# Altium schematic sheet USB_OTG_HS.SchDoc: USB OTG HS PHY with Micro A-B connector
size A4; Date: 25-FEB-2015; Author: A.B; CompanyName: STMicroelectronics; Address1: 12, Rue Jules HOROWITZ; Address2: 38019 Grenoble; Address3: FRANCE; DocumentNumber: MB1191; Revision: B-02; SheetNumber: 10; SheetTotal: 13; Project: STM32F746G-DISCO
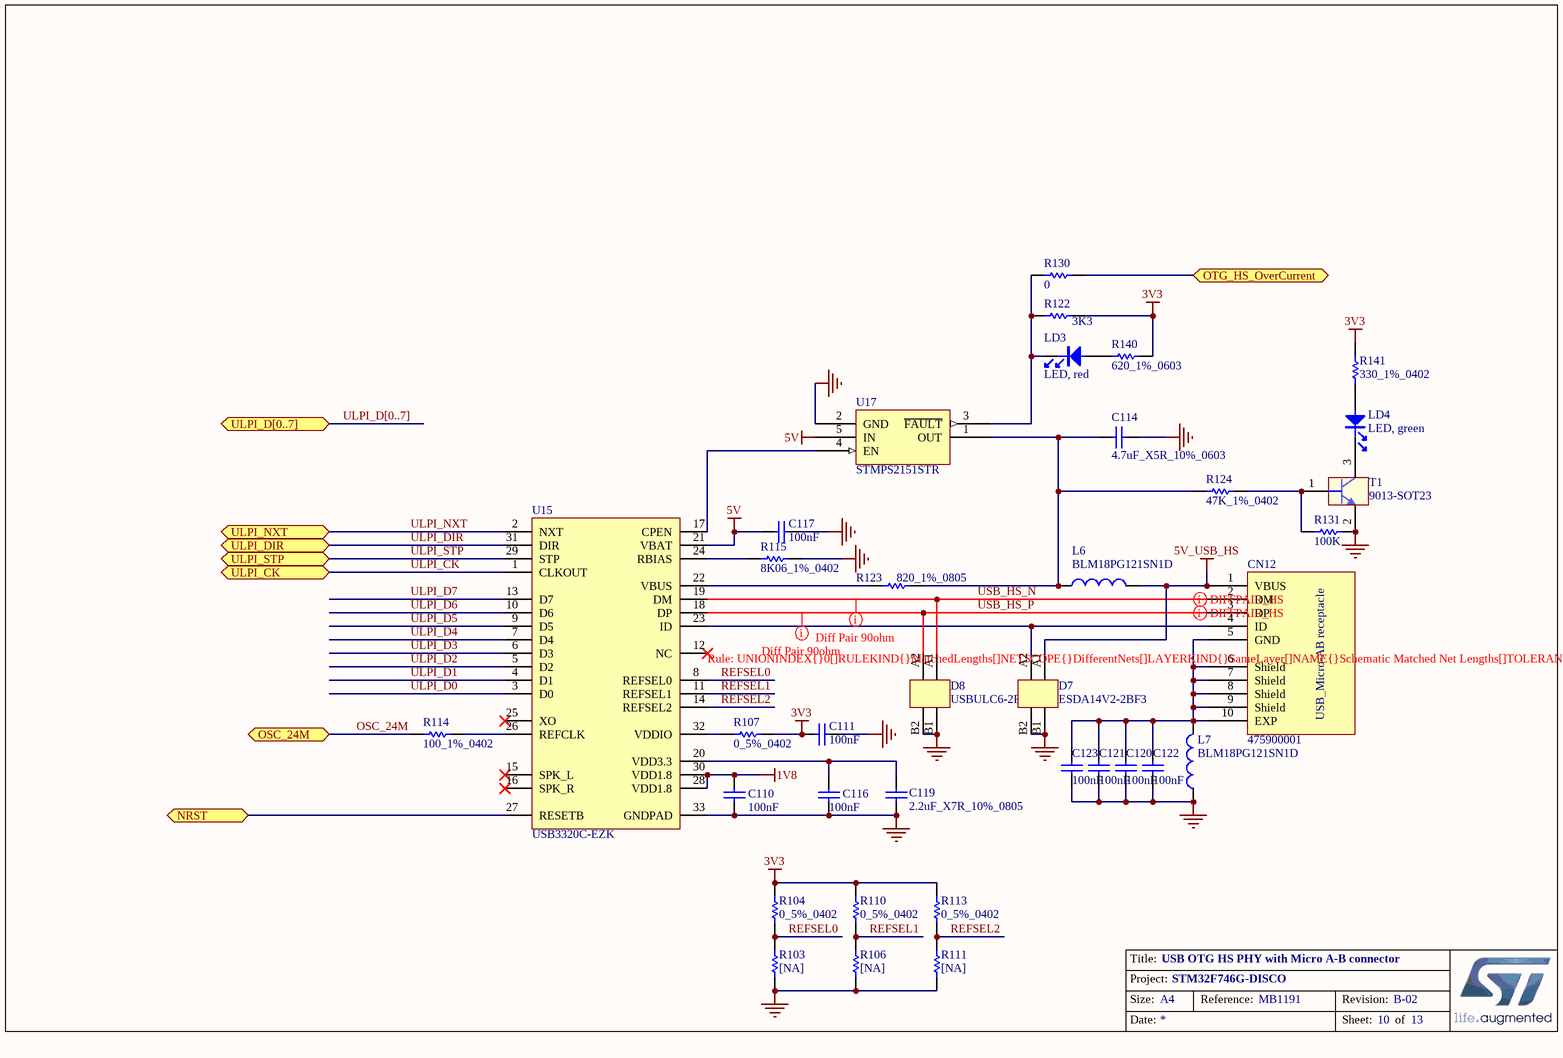
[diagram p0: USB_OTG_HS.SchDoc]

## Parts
C110  100nF  [0402C]
C111  100nF  [0402C]
C114  4.7uF_X5R_10%_0603  [0603C]
C116  100nF  [0402C]
C117  100nF  [0402C]
C119  2.2uF_X7R_10%_0805  [TAN-A]
C120  100nF  [0402C]
C121  100nF  [0402C]
C122  100nF  [0402C]
C123  100nF  [0402C]
CN12  475900001  [USB-MICRO-AB]
D7  ESDA14V2-2BF3  [BGA4_1X1]
D8  USBULC6-2F3  [BGA4_1X1]
L6  BLM18PG121SN1D  [0603L]
L7  BLM18PG121SN1D  [0603L]
LD3  LED, red  [0603D]
LD4  LED, green  [0603D]
R103  [NA]  [0402R]
R104  0_5%_0402  [0402R]
R106  [NA]  [0402R]
R107  0_5%_0402  [0402R]
R110  0_5%_0402  [0402R]
R111  [NA]  [0402R]
R113  0_5%_0402  [0402R]
R114  100_1%_0402  [0402R]
R115  8K06_1%_0402  [0402R]
R122  3K3  [0402R]
R123  820_1%_0805  [0805R]
R124  47K_1%_0402  [0402R]
R130  0  [0402R]
R131  100K  [0402R]
R140  620_1%_0603  [0603R]
R141  330_1%_0402  [0402R]
T1  9013-SOT23  [SOT23]
U15  USB3320C-EZK  [QFN32_0R5_5X5]
U17  STMPS2151STR  [SOT23-5L]

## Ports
NRST, OSC_24M, OTG_HS_OverCurrent, ULPI_CK, ULPI_D[0..7], ULPI_DIR, ULPI_NXT, ULPI_STP

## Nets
1V8: C110.2 U15.28(VDD1.8) U15.30(VDD1.8)
3V3: C111.1 R104.2 R107.2 R110.2 R113.2 R122.1 R140.2 R141.2
5V: C117.1 U15.21(VBAT) U17.5(IN)
5V_USB_HS: CN12.1(VBUS) D7.A1 L6.2
GND: C110.1 C111.2 C114.2 C116.1 C117.2 C119.1 C120.1 C121.1 C122.1 C123.1 D7.B1 D7.B2 D8.B1 D8.B2 L7.1 R103.1 R106.1 R111.1 R115.2 R131.2 T1.2(E) U15.33(GNDPAD) U17.2(GND)
NRST: U15.27(RESETB) ; port NRST
OSC_24M: R114.1 ; port OSC_24M
OTG_HS_OverCurrent: R130.2 ; port OTG_HS_OverCurrent
REFSEL0: R103.2 R104.1 U15.8(REFSEL0)
REFSEL1: R106.2 R110.1 U15.11(REFSEL1)
REFSEL2: R111.2 R113.1 U15.14(REFSEL2)
ULPI_CK: U15.1(CLKOUT) ; port ULPI_CK
ULPI_D0: U15.3(D0)
ULPI_D1: U15.4(D1)
ULPI_D2: U15.5(D2)
ULPI_D3: U15.6(D3)
ULPI_D4: U15.7(D4)
ULPI_D5: U15.9(D5)
ULPI_D6: U15.10(D6)
ULPI_D7: U15.13(D7)
ULPI_DIR: U15.31(DIR) ; port ULPI_DIR
ULPI_NXT: U15.2(NXT) ; port ULPI_NXT
ULPI_STP: U15.29(STP) ; port ULPI_STP
USB_HS_N: CN12.2(DM) D8.A1 U15.19(DM)
USB_HS_P: CN12.3(DP) D8.A2 U15.18(DP)
NetC114_1: C114.1 L6.1 R123.2 R124.1 U17.1(OUT)
NetC116_2: C116.2 C119.2 U15.20(VDD3.3)
NetC120_2: C120.2 C121.2 C122.2 C123.2 CN12.5(GND) CN12.6(Shield) CN12.7(Shield) CN12.8(Shield) CN12.9(Shield) CN12.10(EXP) L7.2
NetCN12_4: CN12.4(ID) D7.A2 U15.23(ID)
NetLD3_1: LD3.1 R140.1
NetLD3_2: LD3.2 R122.2 R130.1 U17.3(~{FAULT})
NetLD4_1: LD4.1 R141.1
NetLD4_2: LD4.2 T1.3(C)
NetR107_1: R107.1 U15.32(VDDIO)
NetR114_2: R114.2 U15.26(REFCLK)
NetR115_1: R115.1 U15.24(RBIAS)
NetR123_1: R123.1 U15.22(VBUS)
NetR124_2: R124.2 R131.1 T1.1(B)
NetU15_17: U15.17(CPEN) U17.4(EN)

Not connected (* = marked no-connect by the designer): U15 12(NC)* 15(SPK_L)* 16(SPK_R)* 25(XO)*

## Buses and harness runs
bus ULPI_D[0..7] = port ULPI_D[0..7]

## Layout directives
differential pair: USB_HS_N, USB_HS_P
rule Matched Net Lengths [Tolerance = 150mil]: USB_HS_N, USB_HS_P

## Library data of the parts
C110 C111 C116 C117 C120-C123 = Cap_100nF_X7R_10%_0402: Capacitor,100nF,16V,X7R,10%,0402,YAGEO; Manuf_Part_1: CC0402KRX7R7BB104
C114 = Cap_4.7uF_X5R_10%_0603: Capacitor,4.7uF,16V, X5R,10%,0603,YAGEO; Manuf_Part_1: CC0603KRX5R7BB475; Order: CC0603KRX5R7BB105
C119 = Cap_2.2uF_X7R_10%_0805: Capacitor,2.2uF,16V, X7R,10%,0805,YAGEO; Manuf_Part_1: CC0805KKX7R7BB225
CN12 = 475900001: USB-MICRO-AB, 47590-0001, SMT, MOLEX
D7 = ESDA14V2-2BF3: Quad bidirectional Transil array for ESD protection; Manuf_1: STM; ECCN_US/EU: EAR99/NEC; Provided: ST; Ref St: 9179040
D8 = USBULC6-2F3: 2-line Transil, (TVS), ultralow capacitance protection for high speed USB; Manuf_1: STM; ECCN_US/EU: EAR99/NEC; Ref St: 9151090; Provided: ST
L6 L7 = BEAD_120R_2A_0603: Bead,120R,2A,0603,BLM18PG121SN1D,MURATA; Manuf_Part_3: FCM1608KF-601T03; Manuf_2: TDK; Manuf_Part_2: MPZ1608S300A; Manuf_3: Tai-tech; Value: 100uH; Description_3: Bead,600R,350mA,0603,FCM1608KF-601T03,Tai-tech; Description_2: Bead,30R,5A,0603,MPZ1608S300A,TDK
LD3 = LED_red: LED, red, 0603; Manuf_1: everlight; Manuf_Part_1: 19-213-R6C-AP1Q2B/3T; Description: LED,red,0603,19-213-R6C-AP1Q2B/3T,everlight; ECCN_US/EU: EAR99/NEC
LD4 = LED_green: LED, green, 0603; Manuf_1: everlight; Manuf_Part_1: 19-213SYGC/S530-E2/TR8; Description: LED,green,0603,19-213SYGC/S530-E2/TR8,everlight; ECCN_US/EU: EAR99/NEC
R103 R106 R111 = Res_NA_0402: Resistor,[NA],0402; Fitted: NO
R104 R107 R110 R113 = Res_0_5%_0402: Resistor,0,0402,5%,YAGEO; Manuf_Part_1: RC0402JR-070RL; Value: 0; Order: 2363467
R114 = Res_100_1%_0402: Resistor,100,0402,1%,YAGEO; Manuf_Part_1: RC0402FR-07100RL; Value: 100; Order: 9239111
R115 = Res_8K06_1%_0402: Resistor,8K06,0402,1%,YAGEO; Manuf_Part_1: RC0402FR-078K06L
R122 = Res_3K3_1%_0402: Resistor,3K3,0402,1%,YAGEO; Manuf_Part_1: RC0402FR-073K3L
R123 = Res_820_1%_0805: Resistor,820,0805,1%,YAGEO; Manuf_Part_1: RC0805FR-07820RL; Value: 820
R124 = Res_47K_1%_0402: Resistor,47K,0402,1%,YAGEO; Manuf_Part_1: RC0402FR-0747KL; Order: 9239430
R130 = Res_0_5%_0402: Resistor,0,0402,5%,YAGEO; Manuf_Part_1: RC0402JR-070RL; Order: 2363467
R131 = Res_100K_1%_0402: Resistor,100K,0402,1%,YAGEO; Manuf_Part_1: RT0402FRE07100KL
R140 = Res_620_1%_0603: Resistor,620,0603,1%,VISHAY; Manuf_Part_1: CRCW0603620RFKEA; Manuf_1: VISHAY DRALORIC; Value: 620; Order: 2122341
R141 = Res_330_1%_0402: Resistor,330,0402,1%,YAGEO; Manuf_Part_1: RC0402FR-07330RL; Value: 330
T1 = 9013-SOT23: NPN Bipolar Transistor; Manuf_1: NXP; Manuf_Part_1: BSR14; Description: NPN Bipolar Transistor, SOT-23 Footprint; Order: 1081310; ECCN_US/EU: EAR99/NEC
U15 = USB3320C-EZK: USB3320C,  Hi-Speed USB Host, Device or OTG PHY with ULPI Low Pin Interface; Manuf_1: MICROCHIP; Manuf_Part_1: USB3320C-EZK-TR
U17 = STMPS2151STR: Enhanced single channel power switches; Manuf_1: STM; Provided: ST; ECCN_US/EU: EAR99/NEC; Ref St: xxxxxx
